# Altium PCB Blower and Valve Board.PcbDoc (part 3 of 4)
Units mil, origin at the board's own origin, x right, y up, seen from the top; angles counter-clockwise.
Board outline 4950 x 3450 mil, 4 copper layers (Top Layer, Signal Layer 1, Signal Layer 2, Bottom Layer), stack 64.4 mil thick; 260 components, 151 nets, 912 pads, 417 vias.
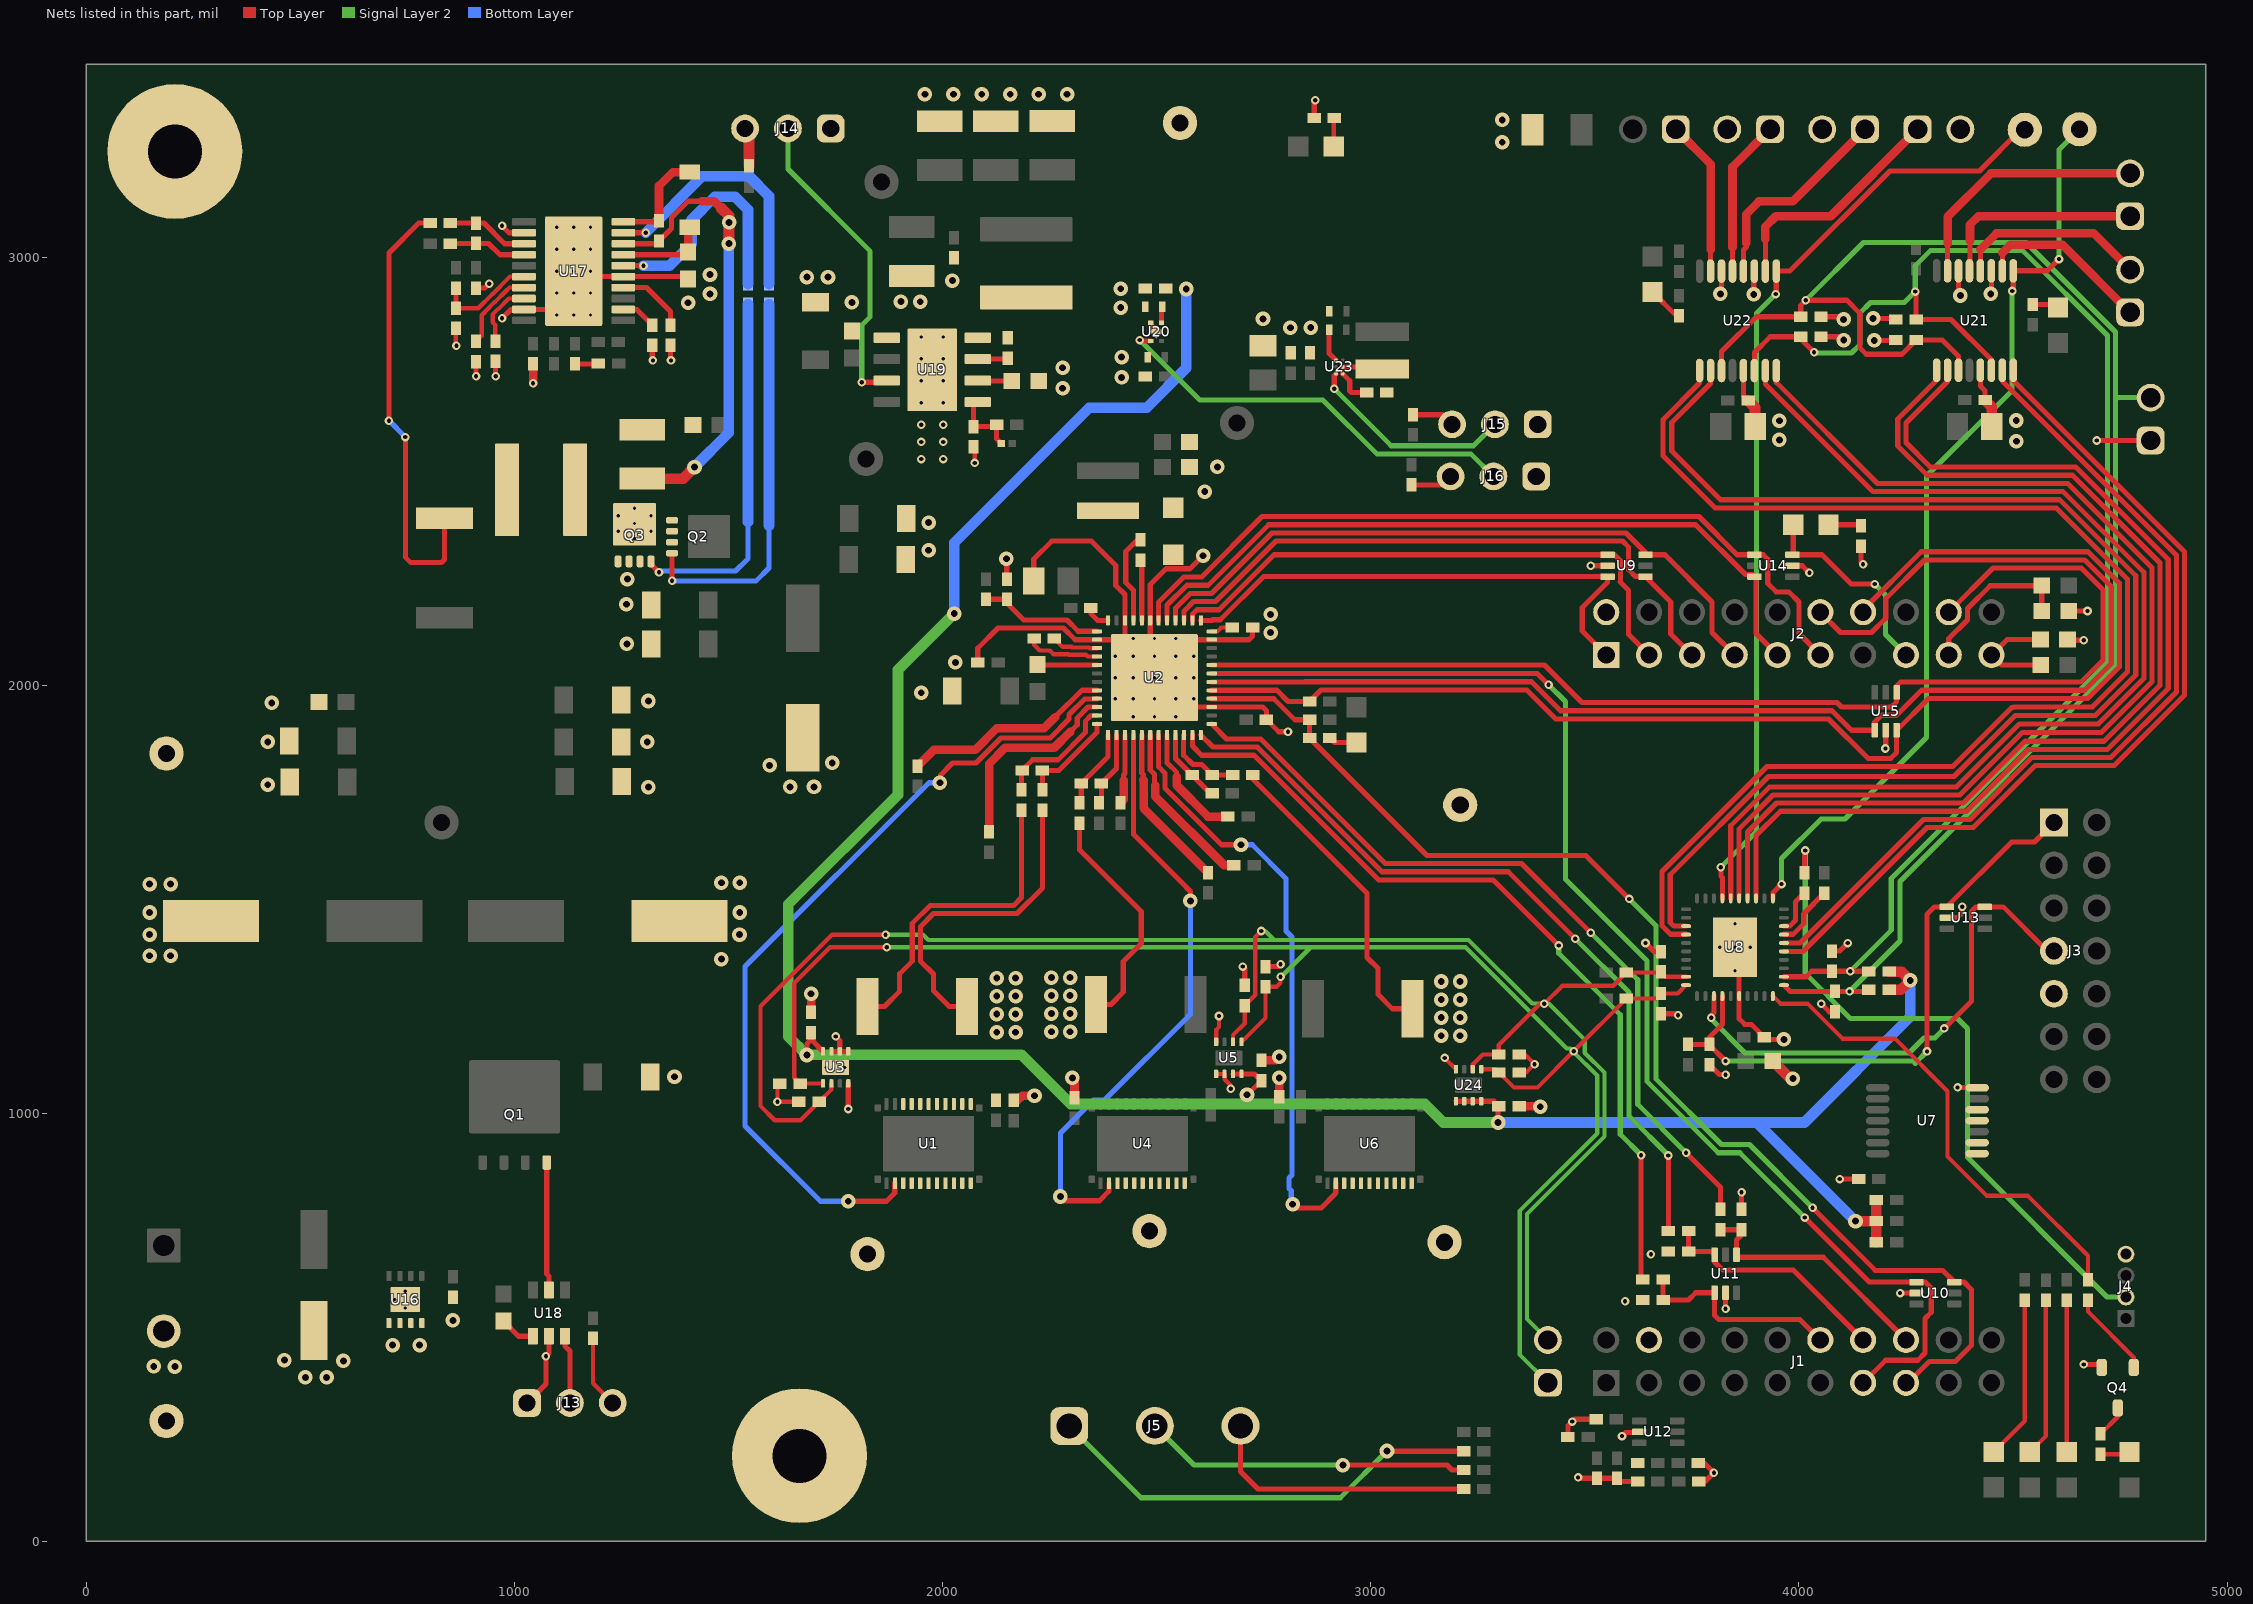
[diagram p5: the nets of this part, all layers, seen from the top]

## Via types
v1: diameter 34, hole 16, Top Layer to Bottom Layer, 186 vias
v2: diameter 20, hole 10, Top Layer to Bottom Layer, 125 vias
v3: diameter 19.68, hole 7.87, Top Layer to Bottom Layer, 94 vias
v4: diameter 19.68, hole 7.87, Top Layer to Bottom Layer, tented both sides, 12 vias

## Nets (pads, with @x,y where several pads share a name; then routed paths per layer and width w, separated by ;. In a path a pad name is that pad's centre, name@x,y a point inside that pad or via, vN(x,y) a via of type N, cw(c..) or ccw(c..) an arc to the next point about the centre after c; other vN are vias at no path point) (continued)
GND: C2.2 C3.2 C4.2 C6.2 C8.2 C9.2 C10.2 C11.2 C12.2 C14.2 C17.2 C19.2 C20.2 C22.2 C23.2 C24.2 C26.2 C27.2 C28.2 C29.2 C30.2 C31.2 C32.2 C33.2 C34.2 C35.2 C36.2 C37.2 C38.2 C39.2 C40.2 C42.2 C43.2 C44.2 C45.2 C46.2 C47.2 C48.2 C49.2 C50.2 C51.2 C52.2 C53.2 C54.2 C55.2 C56.2 C57.2 C59.2 C63.2 C65.2 C66.2 C67.2 C68.2 C71.2 C72.2 C73.2 C74.2 C75.2 C76.2 C77.2 C78.2 C79.2 C80.2 C81.2 C82.2 C83.2 C84.2 C85.2 C86.2 C87.2 C88.2 C89.2 C90.2 C91.2 C92.2 C93.2 C94.2 C95.2 C96.2 D2.2 H1.1 H2.1 J1.4 J2.2 J3.9 J4.4 J6.2 J9.2 J10.2 J11.2 J13.1 J14.1 J15.1 J16.1 Q3.1 Q3.2 Q3.3 Q4.2 R3.1 R4.1 R5.1 R8.1 R12.1 R14.1 R15.1 R16.1 R22.1 R24.1 R25.1 R38.1 R39.1 R47.1 R48.1 R52.1 R53.1 R57.1 R59.1 R60.1 R68.1 R69.1 TP20.1 TP21.1 TP22.1 TP23.1 U2.2 U2.27 U2.35 U2.43 U2.46 U2.49 U3.4 U3.5 U3.6 U3.7 U5.4 U5.5 U5.6 U7.1 U7.2 U7.4 U7.5 U7.7 U8.6 U8.41 U9.2 U10.2 U11.2 U12.2 U13.2 U14.2 U15.2 U16.5 U16.6 U16.7 U16.8 U16.9 U17.2 U17.9 U17.15 U17.21@1138.29,2967.06 U18.2 U19.1 U19.9 U20.2 U20.5 U21.3 U21.6 U21.13 U22.3 U22.6 U22.13 U23.A1 U24.4 | length 8397.9
  Top Layer w10: R47.1@863.01,2833.1 863.01,2794.26 v2(864.45,2792.82) ; C12.2@1620.08,1069.07 1614.17,1063.16 v2(1614.17,1026.98) C11.2@1664.06,1026.98 ; R57.1@2072.27,2556.76 2075.33,2553.69 v2(2075.33,2518.97) ; U5.5@2638.95,1091.91 U5.6@2658.63,1091.91 2658.63,1079.64 2673,1065.27 v2(2673,1057.37) ; U5.4@2638.95,1166.71 2638.95,1194.83 2645.46,1201.34 v2(2645.46,1227.27) ; v2(3172.46,1129.31) U24.4@3198.82,1102.95 ; C96.2@3346.26,1095.08 3362.86,1095.08 v2(3382.64,1114.86) 3360.1,1137.4 C95.2@3346.26,1137.4
  Top Layer w12: v2(910.25,2721.39) C65.2@910.25,2755.69 ; C59.2@910.25,2927.6 910.3,2927.66 930.75,2927.66 v2(940.72,2937.63) ; R53.1@955.71,2756.45 955.71,2722.12 v2(956.43,2721.39) ; v2(970.89,2856.72) 991.66,2877.49 U17.9@1022.14,2877.49 1096.83,2877.49 1138.29,2918.94 v3(1138.29,2967.06) 1151.08,2954.26 U17.15@1254.43,2954.26 1399.48,2954.26 C63.2@1405.39,2948.36 ; v2(970.89,3072.83) 987.11,3056.62 U17.2@1022.14,3056.62 ; J13.1@1029.34,323.43 1073.43,367.52 v2(1073.43,432.77) 1080.24,439.57 U18.2@1080.24,479.36 ; R52.1@1321.88,2793.85 1321.88,2759.86 v2(1323.32,2758.42) ; C66.2@1364.11,2793.85 1364.11,2759.79 v2(1365.48,2758.42) ; U3.7@1740.16,1144.49 U3.6@1759.84,1144.49 ; v2(1750.29,1179.58) 1759.84,1170.03 U3.6@1759.84,1144.49 ; v2(1779.53,1010.02) U3.4@1779.53,1069.68 ; U3.5@1779.53,1144.49 U3.6@1759.84,1144.49 ; R5.1@2056.61,1249.42 2015.28,1249.42 1978.35,1286.35 1978.35,1325.09 1948.13,1355.31 1948.13,1435.81 1978.86,1466.54 2173.92,1466.54 2233.23,1525.85 R16.1@2233.23,1708.3 ; C4.2@2082.17,2052.99 2082.17,2086.1 2129.47,2133.39 2282.31,2133.39 2309.56,2106.14 U2.2@2360.88,2106.14 2406.15,2106.14 U2.49@2425.84,2086.45 ; v1(2148.8,2295.36) 2149.89,2294.26 R22.1@2149.89,2247.87 ; C22.2@2212.96,2243.67 2212.96,2294.38 2254.93,2336.35 2347.46,2336.35 2404.19,2279.62 2404.19,2233.08 2425.84,2211.43 U2.46@2425.84,2151.41 U2.49@2425.84,2086.45 ; R12.1@2319.68,1677.65 2319.68,1615.5 2463.92,1471.26 2463.92,1396.48 2421.9,1354.46 2421.9,1283.01 2393,1254.11 R15.1@2358.51,1254.11 ; U20.2@2485.91,2846.26 2485.91,2842.44 2492.4,2835.96 2492.4,2831.51 U20.5@2498.7,2825.2 ; v1(2608.27,2302.09) 2577.97,2271.79 2521.64,2271.79 2484.89,2235.04 U2.43@2484.89,2151.41 U2.49@2484.89,2027.4 ; v2(2701.23,1342.65) 2705.61,1338.27 C27.2@2705.61,1298.89 ; C9.2@2723.84,2134.68 2723.84,2114.36 2715.62,2106.14 U2.35@2628.59,2106.14 2583.32,2106.14 v3(2544.34,2067.16) v3(2494.73,2017.56) ; R8.1@2724.85,1789.88 2724.85,1780.36 2991.44,1513.78 2991.44,1364.08 3016.74,1338.78 3016.74,1277.92 3050.39,1244.27 R25.1@3097.1,1244.27 ; C28.2@2754.18,1342.65 2783.61,1342.65 v2(2789.39,1348.43) ; v2(2806.66,1891.1) 2784.85,1891.1 2756.82,1919.13 C19.2@2756.15,1919.13 2756.15,1940.03 2747.52,1948.66 U2.27@2628.59,1948.66 2563.63,1948.66 v3(2544.34,1967.95) v3(2494.73,2017.56) ; R59.1@2867.96,3325.03 2867.96,3363.73 v2(2870.38,3366.14) ; C93.2@2902.63,2829.85 2902.63,2775.02 U23.A1@2918.77,2758.88 ; R3.1@3460.63,244.09 3460.63,270.16 v2(3470.47,280) 3475.91,285.43 C6.2@3526.38,285.43 ; v2(3484.25,149.41) 3486.22,147.45 R4.1@3528.35,147.45 C8.2@3575,147.44 3582.5,139.95 R14.1@3623.5,139.95 ; v2(3513.78,2279.01) U9.2@3553.15,2279.01 ; v2(3586.81,246.06) 3594.78,254.03 3625.09,254.03 U12.2@3626.97,255.91 ; v2(3641.73,1397.77) 3661.67,1377.83 C36.2@3677.81,1377.83 ; C37.2@3677.81,1232.58 3714.18,1232.58 v2(3717.76,1229) ; C29.2@3765,182.88 3778.99,182.88 v2(3801.42,160.45) 3780.92,139.95 R24.1@3766.38,139.95 ; C40.2@3790.76,1113.78 3814.33,1090.2 v2(3828.74,1090.2) ; v1(3816.66,2914) 3819.24,2916.58 U22.6@3819.24,2967.17 ; v2(3828.74,543.56) U11.2@3828.74,580.79 ; v3(3850.63,1387.92) 3860.47,1378.08 U8.6@3860.47,1273.75 3860.47,1220.64 3873.33,1207.79 3888.55,1207.79 C35.2@3918.68,1177.66 3923.7,1172.65 v1(3964.8,1172.65) v1@3959.78,1177.66 ; C32.2@3866.09,775.37 v2(3866.09,815.39) ; U22.13@3870.43,2734.88 3870.43,2675.83 C82.2@3881.25,2665 ; v1(3894.36,2912.79) 3894.36,2965.52 U22.3@3896.02,2967.17 ; U14.2@3984.64,2279.01 4007.92,2279.01 v2(4024.65,2262.28) ; C86.2@4051.59,2813.74 4096.9,2813.74 v1(4104.65,2806) ; C85.2@4051.59,2860.54 4098.12,2860.54 v1(4104.33,2854.33) ; v2(4052.01,1256.08) 4070.75,1237.33 C39.2@4084.65,1237.33 ; C38.2@4077.25,1379.04 4095.58,1379.04 v2(4114.17,1397.64) ; v2(4095.58,846.46) C30.2@4139.76,846.46 ; R60.1@4144.77,2324.92 4144.77,2287.49 v2(4149.92,2282.34) ; v1(4173.23,2856.76) 4223.95,2856.76 C84.2@4226.38,2854.33 ; v1(4175.92,2805.12) 4225.49,2805.12 C83.2@4226.38,2806 ; v2(4202,1852.04) 4202.76,1852.8 U15.2@4202.76,1894.69 ; v2(4236.2,580.08) U10.2@4274.61,580.08 ; U13.2@4345.47,1456.63 4370.08,1456.63 4381.31,1467.86 v2(4381.31,1482.22) ; v2(4370.51,1060.35) 4415.52,1060.35 U7.7@4416.34,1059.53 ; U21.6@4372.76,2967.84 4372.76,2918.48 4377.26,2913.97 v1(4377.26,2910.08) ; U21.13@4423.94,2735.56 4423.94,2698.38 4434.77,2687.55 C88.2@4434.77,2665.68 ; v1(4448.2,2914) 4449.53,2915.33 U21.3@4449.53,2967.84 ; R39.1@4627.17,2106.3 4628.46,2105 v2(4665.35,2105) ; R38.1@4630.18,2173.23 v2(4673.99,2173.23) ; v2(4665.35,413.39) 4700.4,413.39 Q4.2@4707.4,406.39 ; U2.49@2425.84,2086.45 v3(2445.13,2067.16) U2.49@2484.89,2027.4 ; U2.49@2484.89,2027.4 v3(2494.73,2017.56)
  Top Layer w20: v2(1043.31,2705.35) R48.1@1043.31,2750.38 ; C10.2@1692.91,1235.47 v1(1692.91,1279.23) ; C2.2@2165.99,1030 2170.85,1034.86 2175.21,1030.49 2185.79,1041.08 v1(2214.57,1041.08) ; C14.2@2308.06,1035.87 v1@2308.06,1076.16 ; C20.2@2744.34,1123.4 2777.67,1123.4 v1(2786.16,1131.89) ; C26.2@2786.16,1038.76 v1(2786.16,1082.85) ; C94.2@3346.26,1016.53 3394.27,1016.53 v1(3395.67,1015.13)
  Top Layer w25: C82.2@3881.25,2665 3897.63,2648.63 C81.2@3897.63,2603.78 ; C34.2@3938.98,1122.05 3979.96,1081.06 v1(3986.09,1081.06) ; C88.2@4434.77,2665.68 4450.51,2649.93 C87.2@4450.51,2604.46
  other v1: 511.5,383.11 561.02,383.11 157.48,408.89 206.69,408.5 600.39,421.84 462.6,423.52 715.45,458.66 778.24,458.66 856.3,516.18 2303.15,1082.68 1373.75,1085.36 3164.71,1181.27 3208.66,1181.27 2126.36,1189.35 2170.31,1189.35 2253.94,1190.53 2297.88,1190.53 3164.71,1223.47 3208.66,1223.47 2126.36,1231.54 2170.31,1231.54 2253.94,1232.72 2297.88,1232.72 3164.71,1265.66 3208.66,1265.66 2126.36,1273.74 2170.31,1273.74 2253.94,1274.91 2297.88,1274.91 3164.71,1307.85 3208.66,1307.85 2126.36,1315.93 2170.31,1315.93 2253.94,1317.1 2297.88,1317.1 1483.28,1360 147.64,1368.11 196.85,1368.11 147.64,1417.45 1525.59,1417.45 147.64,1468.95 1526.16,1468.95 147.64,1535.43 196.85,1535.43 1483.28,1538.38 1526.16,1538.38 1312.65,1761.81 1643.7,1762.5 1699.5,1762.5 423.69,1767.5 1595.7,1812.59 1742.13,1818.26 423.69,1867.31 1310.13,1867.31 433.07,1958.66 1312.65,1962.98 1950.21,1982.12 2029.94,2052.99 1262.54,2096.46 2765.94,2122.69 2765.94,2165.35 1261.47,2188.98 1263.77,2247.87 1967.18,2314.94 1967.18,2379.72 2612.18,2451.94 2641.66,2509.84 4507.87,2569.71 3954.34,2572.96 3954.34,2617.7 4507.79,2618.11 2280.08,2693.64 2417.96,2718.69 2280.32,2741.43 2417.96,2766.14 2812.24,2834.65 2859.8,2835.04 2748.27,2855.45 2415.99,2881.82 1405.39,2893.03 1787.96,2894.03 1947.78,2895.36 1902.39,2895.99 1456.69,2914 2415.99,2926 2022.82,2944.88 1683.07,2953.08 1732.28,2953.08 1456.69,2959.08 3307.09,3268.14 3307.09,3320.34 1958.66,3380 2025.07,3380 2091.48,3380 2157.88,3380 2224.29,3380 2290.7,3380
  other v2: 3593.92,561.17 3654.27,670.97 1950.21,2528.08 2001.39,2528.08 1950.21,2568.18 2001.39,2568.18 1950.21,2608.29 2001.39,2608.29
  other v3: 745.08,545.28 720.47,564.96 769.68,564.96 745.08,584.65 3850.63,1332.8 3815.2,1387.92 3886.06,1387.92 3850.63,1443.04 2445.13,1926.02 2494.73,1926.02 2544.34,1926.02 2403.2,1967.95 2445.13,1967.95 2494.73,1967.95 2586.27,1967.95 2403.2,2017.56 2445.13,2017.56 2544.34,2017.56 2586.27,2017.56 2403.2,2067.16 2494.73,2067.16 2586.27,2067.16 2445.13,2109.09 2494.73,2109.09 2544.34,2109.09 1950.21,2710.82 2001.39,2710.82 1950.21,2762 2001.39,2762 1098.91,2915.88 1138.29,2915.88 1177.65,2915.88 1098.91,2967.06 1177.65,2967.06 1098.91,3018.24 1138.29,3018.24 1177.65,3018.24
  other v4: 1950.21,2659.64 2001.39,2659.64 1950.21,2813.18 2001.39,2813.18 1098.91,2864.69 1138.29,2864.69 1177.65,2864.69 1098.91,3069.42 1138.29,3069.42 1177.65,3069.42
"IN1 DRV8-1": U8.15 U21.16 | length 2108.5
  Top Layer w12: U8.15@3964.8,1378.08 4009.69,1378.08 4299.11,1667.5 4407.27,1667.5 4551.87,1812.09 4736.41,1812.09 4900.63,1976.32 4900.63,2311.46 4500.71,2711.38 U21.16@4500.71,2735.56
"IN1 DRV8-2": U8.25 U22.16 | length 2619.6
  Top Layer w12: U8.25@3860.47,1502.1 3860.47,1664.38 3939.6,1743.5 4375.79,1743.5 4520.39,1888.09 4520.44,1888.09 4522.11,1889.76 4706.59,1889.76 4824.63,2007.8 4824.63,2274.48 4628.13,2470.98 4183.57,2470.98 3947.2,2707.35 U22.16@3947.2,2734.88
"IN2 DRV8-1": U8.16 U21.15 | length 2079.5
  Top Layer w12: U8.16@3964.8,1397.77 4002.5,1397.77 4291.24,1686.5 4399.4,1686.5 4544,1831.09 4728.54,1831.09 4881.63,1984.19 4881.63,2303.59 4475.12,2710.1 U21.15@4475.12,2735.56
"IN2 DRV8-2": U8.26 U22.15 | length 2622.6
  Top Layer w12: U8.26@3840.79,1502.1 3840.79,1671.56 3931.73,1762.5 4367.92,1762.5 4514.87,1909.45 4699.41,1909.45 4805.63,2015.67 4805.63,2263.58 4617.23,2451.98 4172.76,2451.98 3921.61,2703.13 U22.15@3921.61,2734.88
"IN3 DRV8-1": U8.23 U21.10 | length 2487.9
  Top Layer w12: U8.23@3899.84,1502.1 3899.84,1648.66 3956.68,1705.5 4391.53,1705.5 4536.13,1850.09 4720.67,1850.09 4862.63,1992.06 4862.63,2293.48 4646.95,2509.16 4307.53,2509.16 4250,2566.69 4250,2612 4347.17,2709.17 U21.10@4347.17,2735.56
"IN3 DRV8-2": U8.33 U22.10 | length 3094
  Top Layer w12: U8.33@3736.46,1437.14 3708.03,1437.14 3699.46,1445.7 3699.46,1557.11 3928.96,1786.61 4362.51,1786.61 4505.04,1929.13 4692.22,1929.13 4786.63,2023.54 4786.63,2255.4 4609.05,2432.98 3817.02,2432.98 3703,2547 3703,2613.67 3793.65,2704.33 U22.10@3793.65,2734.88
"IN4 DRV8-1": U8.24 U21.9 | length 2486.3
  Top Layer w12: U8.24@3880.16,1502.1 3880.16,1657.19 3947.47,1724.5 4383.66,1724.5 4528.26,1869.09 4712.8,1869.09 4843.63,1999.93 4843.63,2285.61 4639.08,2490.16 4299.66,2490.16 4231,2558.82 4231,2621.5 4321.58,2712.08 U21.9@4321.58,2735.56
"IN4 DRV8-2": U8.34 U22.9 | length 3126.7
  Top Layer w12: U8.34@3736.46,1417.45 3735.77,1418.14 3700.16,1418.14 3680.46,1437.83 3680.46,1564.98 3925.53,1810.04 4359.08,1810.04 4497.17,1948.13 4501.01,1948.13 4501.69,1948.82 4685.04,1948.82 4767.63,2031.41 4767.63,2247.53 4601.18,2413.98 3804.39,2413.98 3682.96,2535.41 3682.96,2620.51 3768.06,2705.61 U22.9@3768.06,2734.88
INHA: J2.1 U2.37 U9.3 | length 1223
  Top Layer w12: U2.37@2603,2151.41 2628.73,2151.41 2630,2152.68 2648.65,2152.68 2749.4,2253.42 U9.3@3553.15,2253.42 3553.15,2240.23 3494.09,2181.18 3494.09,2126.38 J2.1@3550,2070.47
INHB: J2.5 U2.39 U9.4 | length 1460.5
  Top Layer w12: U2.39@2563.63,2151.41 2563.63,2172.67 2586.19,2195.23 2637.46,2195.23 2778.85,2336.61 3588.07,2336.61 3602.36,2322.32 3602.36,2269.38 3618.32,2253.42 U9.4@3641.73,2253.42 3700.79,2194.37 3700.79,2119.68 J2.5@3750,2070.47
INHC: J2.9 U2.41 U14.6 | length 1740.6
  Top Layer w12: U2.41@2524.26,2151.41 2524.26,2187.04 2570.45,2233.23 2620.19,2233.23 2761.57,2374.61 3758.62,2374.61 3875.09,2258.14 3891.34,2258.14 U14.6@3896.06,2253.42 3899.84,2249.64 3899.84,2120.63 J2.9@3950,2070.47
INLA: J2.3 U2.38 U9.1 | length 1325.5
  Top Layer w12: U2.38@2583.32,2151.41 2583.32,2165.49 2594.06,2176.23 2645.33,2176.23 2773.71,2304.61 U9.1@3553.15,2304.61 3569.4,2304.61 3582.88,2291.12 3582.88,2241.11 3582.68,2240.91 3602.36,2221.22 3602.36,2118.11 J2.3@3650,2070.47
INLB: J2.7 U2.40 U9.6 | length 1570.2
  Top Layer w12: U2.40@2543.95,2151.41 2543.95,2179.86 2578.32,2214.23 2628.06,2214.23 2769.44,2355.61 3595.94,2355.61 3641.73,2309.82 U9.6@3641.73,2304.61 3687.12,2304.61 3797.31,2194.41 3797.31,2123.16 J2.7@3850,2070.47
INLC: J2.11 U2.42 U14.4 | length 1881
  Top Layer w12: U2.42@2504.58,2151.41 2504.58,2194.23 2562.58,2252.23 2604.52,2252.23 2745.91,2393.61 3766.49,2393.61 3855.5,2304.61 U14.4@3896.06,2304.61 3916.59,2304.61 3927.17,2294.03 3927.17,2237.66 3946.85,2217.97 3976.38,2217.97 4000,2194.35 4000,2120.47 J2.11@4050,2070.47
ISENA: C32.1 J1.16 R27.2 U11.4 | length 590.8
  Top Layer w12: R27.2@3816.93,728.13 C32.1@3866.09,728.13 3866.09,716.06 3854.33,704.3 U11.4@3854.33,669.37 3860.03,663.67 4056.8,663.67 J1.16@4250,470.47
ISENB: C33.1 J1.14 R28.2 U11.6 | length 550.7
  Top Layer w12: R28.2@3742.36,724.74 C33.1@3742.36,677.17 3795.35,677.17 U11.6@3803.15,669.37 3803.15,652.56 3821.94,633.76 3986.71,633.76 J1.14@4150,470.47
ISENC: C31.1 J1.12 R26.2 U11.1 | length 498.4
  Top Layer w12: R26.2@3682.96,612.11 C31.1@3682.96,564.06 3742.23,564.06 3758.96,580.79 U11.1@3803.15,580.79 3803.15,528.43 3813.6,517.97 4002.5,517.97 J1.12@4050,470.47
LDO3.3: C10.1 C20.1 C79.1 C80.1 C94.1 R6.2 R17.2 R32.2 R33.2 R72.2 U3.8 U5.7 U5.8 U20.1 U24.5 U24.6 U24.7 U24.8 | length 6067.5
  Top Layer w12: v1(1683.07,1136.2) 1683.07,1162.2 1692.91,1172.05 U3.8@1720.47,1144.49 ; U20.1@2511.5,2846.26 2511.5,2882.17 C80.1@2513.19,2883.86 ; U5.7@2678.32,1091.91 U5.8@2698,1091.91 2728.59,1091.91 C20.1@2744.34,1076.16 2711.66,1043.48 v1(2710.88,1043.48) ; U24.5@3198.82,1028.15 U24.6@3218.5,1028.15 U24.7@3238.19,1028.15 U24.8@3257.87,1028.15 3287.41,1028.15 C94.1@3299.02,1016.53 3297.24,1014.76 v1(3297.24,978.52)
  Top Layer w25: v1(4132.1,748.03) R6.2@4180.89,748.03 ; R17.2@4180.89,698.82 R6.2@4180.89,748.03 ; R72.2@4180.89,797.24 R6.2@4180.89,748.03 ; R33.2@4210.61,1288.47 4237.96,1288.47 v1(4259.9,1310.41) 4239.49,1330.82 R32.2@4210.61,1330.82
  Signal Layer 2 w25: v1(2026.98,2167.26) 1895.59,2035.87 1895.59,1743.96 1639.69,1488.06 1639.69,1179.58 v1(1683.07,1136.2) 1683.3,1136.43 2184.18,1136.43 2298.98,1021.63 3125.92,1021.63 3169.03,978.52 v1(3297.24,978.52)
  Bottom Layer w25: v1(2026.98,2167.26) 2026.98,2332.73 2342.34,2648.09 2476.5,2648.09 2569.14,2740.74 v1(2569.14,2925.26) ; v1(3297.24,978.52) 3907.48,978.52 ; v1(4132.1,748.03) 3907.48,972.65 3907.48,978.52 ; v1(4259.9,1310.41) 4259.9,1225.47 4012.94,978.52 3907.48,978.52
LED: D5.1 J2.15 U14.3 | length 487.5
  Top Layer w12: D5.1@3986.63,2374.61 3986.63,2306.59 U14.3@3984.64,2304.61 4053.66,2304.61 4122.25,2236.01 v2(4177.17,2236.01)
  Signal Layer 2 w12: v2(4177.17,2236.01) 4202.36,2210.82 4202.36,2118.11 J2.15@4250,2070.47
MCUON: R67.1 U8.10 | length 1133.1
  Top Layer w10: U8.10@3939.21,1273.75 3956.88,1256.08 4020.24,1256.08 4101.92,1174.4 4224.37,1174.4 4347.17,1051.6 4347.17,898.9 4438.98,807.09 4535.28,807.09 4675.15,667.22 R67.1@4675.15,610.71
MOTA: J5.1 R2.2 TP2.1 U1.3 U1.4 U1.5 U1.6 U1.7 U1.8 U1.9 U1.10 U1.11 | length 1036.3
  Top Layer w12: v1(3037.87,211.2) 3038.47,210.6 R2.2@3217.13,210.6
  Signal Layer 2 w12: J5.1@2295.7,269.86 2463.42,102.13 2928.8,102.13 v1(3037.87,211.2)
MOTB: J5.2 R11.2 TP8.1 U4.3 U4.4 U4.5 U4.6 U4.7 U4.8 U4.9 U4.10 U4.11 | length 764.2
  Top Layer w12: v1(2935.04,178.43) 3177.87,178.43 3189.68,166.62 R11.2@3217.13,166.62
  Signal Layer 2 w12: J5.2@2495.7,269.86 2587.12,178.43 v1(2935.04,178.43)
MOTC: J5.3 R23.2 TP11.1 U6.3 U6.4 U6.5 U6.6 U6.7 U6.8 U6.9 U6.10 U6.11 | length 644.8
  Top Layer w12: J5.3@2695.7,269.86 2695.7,163.36 2736.42,122.63 R23.2@3217.13,122.63
NetC5_2: C5.2 U2.5 | length 140.1
  Top Layer w12: C5.2@2221.11,2048 2222.03,2047.08 U2.5@2360.88,2047.08
NetC7_1: C7.1 U2.4 | length 173
  Top Layer w10: C7.1@2213.93,2108.58 2213.93,2093.64 2226.75,2080.81 2250.22,2080.81 2258.59,2072.44 2293.76,2072.44 2295.07,2071.14 2334.66,2071.14 2339.03,2066.77 U2.4@2360.88,2066.77
NetC7_2: C7.2 U2.3 | length 108.9
  Top Layer w10: C7.2@2261.17,2108.58 2280.32,2089.44 2300.8,2089.44 2302.11,2088.14 2341.7,2088.14 2343.39,2086.45 U2.3@2360.88,2086.45
NetC9_1: C9.1 U2.36 | length 51.7
  Top Layer w10: U2.36@2628.59,2125.82 2642.15,2125.82 2651.01,2134.68 C9.1@2676.6,2134.68
NetC15_1: C15.1 R7.2 U2.21 | length 173.4
  Top Layer w12: U2.21@2543.95,1883.7 2543.95,1828.54 C15.1@2582.61,1789.88 2621.98,1750.51 R7.2@2629.85,1750.51
NetC15_2: C15.2 R8.2 U2.22 | length 181.5
  Top Layer w12: U2.22@2563.63,1883.7 2562.95,1883.01 2562.95,1836.41 2584.67,1814.69 2605.04,1814.69 C15.2@2629.85,1789.88 R8.2@2677.61,1789.88
NetC16_1: C16.1 R9.2 U2.14 | length 175.9
  Top Layer w12: R9.2@2364.96,1724.9 2370.86,1730.8 C16.1@2370.86,1770.17 2406.15,1805.46 U2.14@2406.15,1883.7
NetC16_2: C16.2 R12.2 U2.13 | length 186.5
  Top Layer w12: R12.2@2319.68,1724.9 2323.62,1728.83 C16.2@2323.62,1770.17 2386.47,1833.02 U2.13@2386.47,1883.7
NetC18_1: C18.1 R13.2 U2.11 | length 289.6
  Top Layer w12: R13.2@2184.3,1755.54 2184.3,1799.64 C18.1@2185.68,1801.02 2210.49,1825.83 2269.83,1825.83 2333.32,1889.32 2333.32,1915.49 2346.8,1928.97 U2.11@2360.88,1928.97
NetC18_2: C18.2 R16.2 U2.12 | length 229.7
  Top Layer w12: R16.2@2233.23,1755.54 2233.23,1800.71 C18.2@2232.92,1801.02 2271.89,1801.02 2360.88,1890.01 U2.12@2360.88,1909.29
NetC21_1: C21.1 U2.44 | length 141.8
  Top Layer w12: C21.1@2462.58,2292.15 2465.21,2289.52 U2.44@2465.21,2151.41
NetC21_2: C21.2 D2.1 L1.1 U2.45 | length 214.2
  Top Layer w12: U2.45@2445.52,2151.41 2445.52,2221.76 2427.81,2239.48 2427.81,2312.21 2454.99,2339.4 C21.2@2462.58,2339.4
NetC41_2: C41.2 R41.2
NetC58_1: C58.1 R46.1 U17.3 | length 191.6
  Top Layer w12: R46.1@850.44,3079.18 910.26,3079.18 C58.1@910.3,3079.13 928.53,3079.13 976.63,3031.03 U17.3@1022.14,3031.03
NetC58_2: C58.2 R45.1 U17.4 | length 183
  Top Layer w12: R45.1@850.44,3031.03 851.3,3031.89 C58.2@910.3,3031.89 939.6,3031.89 966.05,3005.44 U17.4@1022.14,3005.44
NetC60_2: C60.2 U18.1 | length 83
  Top Layer w12: C60.2@974.41,514.6 1009.65,479.36 U18.1@1042.83,479.36
NetC61_2: C61.2 R51.2 | length 54.5
  Top Layer w12: C61.2@1141.7,2750.19 1194.47,2750.19 R51.2@1195.72,2751.44
NetC63_1: C63.1 D3.2 U17.17 | length 213.1
  Top Layer w12: U17.17@1254.43,3005.44 1399.48,3005.44 C63.1@1405.39,3011.35
  Top Layer w20: C63.1@1405.39,3011.35 1405.39,3065.99 D3.2@1408.95,3069.55
NetC64_1: C64.1 L2.2 Q2.1 Q2.2 Q2.3 Q3.5 Q3.6 Q3.7 Q3.8 Q3.9 R41.1 U17.18 | length 1119.1
  Top Layer w12: U17.18@1254.43,3031.03 1331.22,3031.03 C64.1@1337.59,3037.4 1366.95,3066.76 1366.95,3092.02 1405.35,3130.41 1437.5,3130.41
  Top Layer w20: 1437.5,3130.41 1466.54,3130.41 1482.56,3114.39
  Top Layer w25: R41.1@1298.94,2482.38 1393.42,2482.38 v1(1420.41,2509.38) ; 1482.56,3114.39 1501.29,3095.66 v1(1501.29,3080.71) 1501.29,3032.13 v1(1500.65,3031.5)
  Bottom Layer w25: v1(1420.41,2509.38) 1500.65,2589.61 v1(1500.65,3031.5) 1500.65,3080.07 v1(1501.29,3080.71)
  other v3: 1280.39,2341.93 1242,2359.74 1318.77,2359.74 1280.39,2377.56 1242,2395.37 1318.77,2395.37
  other v4: 1280.39,2413.19
NetC64_2: C64.2 D3.1 U17.20 | length 250.2
  Top Layer w12: U17.20@1254.43,3082.21 1335.16,3082.21 C64.2@1337.59,3084.65
  Top Layer w20: C64.2@1337.59,3084.65 1337.59,3165.82 1370.27,3198.49 D3.1@1408.95,3198.49
NetC65_1: C65.1 U17.7 | length 192.3
  Top Layer w10: C65.1@910.25,2802.94 923.72,2816.4 923.72,2864.15 931.89,2872.32 931.89,2872.88 954.74,2895.72 955.29,2895.72 979.65,2920.08 988.24,2928.67 U17.7@1022.14,2928.67
NetC66_1: C66.1 U17.14 | length 164.6
  Top Layer w12: U17.14@1254.43,2928.67 1308.29,2928.67 1364.11,2872.86 C66.1@1364.11,2841.09
NetC69_1: C69.1 U19.7 | length 71
  Top Layer w12: U19.7@2082.1,2761.41 2149.3,2761.41 C69.1@2151.97,2764.08
NetC69_2: C69.2 L3.1 U19.8
NetC70_2: C70.2 R56.1 R57.2 U19.5 | length 165.4
  Top Layer w12: U19.5@2082.1,2661.41 2072.27,2651.58 R57.2@2072.27,2604 2121.88,2604 R56.1@2126.15,2608.27 2126.15,2575.07 C70.2@2136.78,2564.44
NetC76_1: C76.1 U19.6 | length 79.6
  Top Layer w12: U19.6@2082.1,2711.41 2082.69,2710.82 C76.1@2161.48,2710.82
NetD1_2: D1.2 R18.2 | length 66.6
  Top Layer w12: R18.2@2904.37,1876.74 2915.32,1865.8 D1.2@2966.39,1865.8
NetD4_2: D4.2 R59.2 | length 67.9
  Top Layer w10: D4.2@2913.32,3257.87 2913.32,3323.14 R59.2@2915.21,3325.03
NetD5_2: D5.2 R60.2 | length 76.5
  Top Layer w12: D5.2@4069.31,2374.61 4142.32,2374.61 R60.2@4144.77,2372.16
NetD6_2: D6.2 R61.2 | length 370
  Top Layer w10: D6.2@4539.37,208.66 4576.77,246.06 R61.2@4576.77,563.14
NetD7_2: D7.2 R62.2 | length 354.8
  Top Layer w10: D7.2@4625.67,208.66 R62.2@4625.67,563.46
NetD8_2: D8.2 R63.2 | length 69.6
  Top Layer w10: R63.2@4704.72,203.86 4767.56,203.86 D8.2@4772.36,208.66
NetD9_2: D9.2 R64.2 | length 62.1
  Top Layer w12: R64.2@4546.24,2889.1 4598.02,2889.1 D9.2@4605.3,2881.82
NetD10_2: D10.2 R65.2 | length 84.8
  Top Layer w12: D10.2@3658.09,2918.48 3713.73,2862.84 R65.2@3719.84,2862.84
NetD11_2: D11.2 R73.2 | length 384.5
  Top Layer w10: D11.2@4454.95,209.02 4527.56,281.63 R73.2@4527.56,563.46
NetJ2_17: J2.17 R36.1 R38.2 | length 381.3
  Top Layer w12: J2.17@4350,2070.47 4350,2108.94 4393.51,2152.45 4393.51,2178.94 4446.82,2232.25 R36.1@4567.19,2232.25 R38.2@4567.19,2173.23
NetJ2_19: J2.19 R37.1 R39.2 | length 253.6
  Top Layer w12: R39.2@4564.17,2106.3 4485.83,2106.3 J2.19@4450,2070.47 4473.23,2047.24 R37.1@4564.96,2047.24
NetJ7_1: J7.1 U21.2 | length 413.2
  Top Layer w12: U21.2@4475.12,2967.84 4475.12,3009.57
  Top Layer w20: 4475.12,3009.57 4493.79,3028.24 4616.04,3028.24 J7.1@4773.62,2870.65
NetJ7_2: J7.2 U21.4 | length 450.2
  Top Layer w12: U21.4@4423.94,2967.84 4423.94,3017.9
  Top Layer w20: 4423.94,3017.9 4461.27,3055.24 4689.04,3055.24 J7.2@4773.62,2970.65
NetJ8_1: J8.1 U21.5 | length 490.6
  Top Layer w12: U21.5@4398.35,2967.84 4399.61,2969.1 4399.61,3038.12
  Top Layer w20: 4399.61,3038.12 4399.61,3075.71 4419.29,3095.4 J8.1@4773.62,3095.4
NetJ8_2: J8.2 U21.7 | length 594.7
  Top Layer w12: U21.7@4347.17,2967.84 4347.17,3031.5
  Top Layer w20: 4347.17,3031.5 4347.17,3094.11 4448.45,3195.4 J8.2@4773.62,3195.4
NetJ9_1: J9.1 U22.2 | length 553.8
  Top Layer w12: U22.2@3921.61,2967.17 3921.61,3041.34
  Top Layer w20: 3921.61,3041.34 3921.61,3071.17 3945.83,3095.4 4074.21,3095.4 J9.1@4277.26,3298.45
NetJ10_1: J10.1 U22.4 | length 495.2
  Top Layer w12: U22.4@3870.43,2967.17 3870.43,3016.21 3877.32,3023.1 3877.32,3032.36
  Top Layer w20: 3877.32,3032.36 3877.32,3100.39 3906.84,3129.92 3985.83,3129.92 J10.1@4154.36,3298.45
NetJ11_1: J11.1 U22.5 | length 367.7
  Top Layer w12: U22.5@3844.84,2967.17 3844.84,3023.1
  Top Layer w20: 3844.84,3023.1 3844.84,3210.51 J11.1@3932.77,3298.45
NetJ12_1: J12.1 U22.7 | length 365
  Top Layer w12: U22.7@3793.65,2967.17 3793.65,3017
  Top Layer w20: J12.1@3712.34,3298.45 3793.65,3217.14 3793.65,3017
NetJ13_2: J13.2 U18.3 | length 160.8
  Top Layer w12: U18.3@1117.64,479.36 1117.64,456.27 1129.34,444.56 J13.2@1129.34,323.43
NetJ13_3: J13.3 R54.1 | length 175.6
  Top Layer w10: R54.1@1183.21,474.47 1183.21,369.57 J13.3@1229.34,323.43
  Top Layer w12: R54.1@1179.34,470.61 R54.1@1183.21,474.47
NetJ14_2: J14.2 U19.3 | length 741.5
  Top Layer w12: v2(1811.02,2707.35) 1839.48,2707.35 1844.45,2712.32 1845.36,2711.41 U19.3@1869.5,2711.41
  Signal Layer 2 w12: J14.2@1638.59,3300.18 1638.59,3205.42 1830.71,3013.3 1830.71,2860.24 1811.02,2840.56 v2(1811.02,2707.35)
NetJ14_3: J14.3 R55.1 | length 91.2
  Top Layer w25: J14.3@1538.59,3300.18 1547.7,3291.07 R55.1@1547.7,3212.79
NetJ15_2: J15.2 U23.C1 | length 487.7
  Top Layer w12: v2(2914.81,2692.12) 2914.84,2723.45 U23.C1@2918.77,2727.38
  Signal Layer 2 w12: v2(2914.81,2692.12) 3047.69,2559.24 3239.88,2559.24 J15.2@3289.88,2609.24
NetJ15_3: J15.3 R70.1 | length 100.2
  Top Layer w12: R70.1@3098.96,2631.65 3167.47,2631.65 J15.3@3189.88,2609.24
NetJ16_2: J16.2 U20.3 | length 983.8
  Top Layer w12: v2(2460.63,2806) 2462.5,2804.14 U20.3@2485.91,2804.14
  Signal Layer 2 w12: v2(2460.63,2806) 2600.96,2665.68 2888.7,2665.68 3014.13,2540.24 3233.73,2540.24 J16.2@3286.47,2487.5
NetJ16_3: J16.3 R71.1 | length 109.1
  Top Layer w12: R71.1@3095.55,2467.57 3183.56,2467.57 3186.47,2470.48 J16.3@3186.47,2487.5
NetL2_1: L2.1 R40.2 R46.2 | length 1048
  Top Layer w12: v2(706.69,2617.87) 706.69,3009.38 776.49,3079.18 R46.2@803.19,3079.18 ; v2(745.08,2579.48) 745.08,2298.92 757.87,2286.12 829.43,2286.12 836.61,2293.31 R40.2@836.61,2389.76
  Bottom Layer w12: v2(706.69,2617.87) v2(745.08,2579.48)
NetL4_1: L4.1 U23.B2 | length 94.4
  Top Layer w12: U23.B2@2934.52,2743.13 3021.7,2743.13 L4.1@3026.79,2738.04
NetQ1_4: Q1.4 U18.5 | length 299.4
  Top Layer w12: Q1.4@1075.49,885.04 1075.49,624.71 1080.24,619.96 U18.5@1080.24,587.63
NetQ2_4: Q2.4 R50.2 | length 919.5
  Top Layer w12: Q2.4@1368.01,2308.28 1368.01,2267.23 1368.11,2267.13 v2(1368.11,2243.67)
  Bottom Layer w12: v2(1368.11,2243.67) 1564.45,2243.67 1594.49,2273.71 1594.49,2372.94
  Bottom Layer w25: 1594.49,2372.94 R50.2@1594.49,2889.76
NetQ3_4: Q3.4 R49.2 | length 848.2
  Top Layer w12: Q3.4@1318.77,2289.07 1318.77,2282.6 v2(1337.59,2263.78)
  Bottom Layer w12: v2(1337.59,2263.78) 1340.49,2266.67 1516.46,2266.67 1545.28,2295.48 1545.28,2381.89
  Bottom Layer w25: 1545.28,2381.89 R49.2@1545.28,2889.76
NetQ4_1: Q4.1 R67.2 | length 201.4
  Top Layer w10: R67.2@4675.15,563.46 4675.15,536.96 4782.2,429.91 Q4.1@4782.2,406.39
NetQ4_3: Q4.3 R63.1 | length 77.4
  Top Layer w10: R63.1@4704.72,251.1 4744.8,291.18 Q4.3@4744.8,311.9
NetR20_1: R20.1 U2.48 | length 59.9
  Top Layer w12: R20.1@2346.46,2180.26 2346.46,2166.65 2361.69,2151.41 U2.48@2386.47,2151.41
NetR21_1: R21.1 R22.2 U2.1 | length 290.8
  Top Layer w12: R21.1@2101.03,2200.63 2141.08,2200.63 2189.31,2152.39 2290.18,2152.39 2316.75,2125.82 U2.1@2360.88,2125.82
NetR29_1: R29.1 U8.18 | length 105.3
  Top Layer w12: U8.18@3964.8,1437.14 3978.71,1437.14 3992.34,1450.76 3992.34,1493.88 R29.1@4012.84,1514.38
NetR34_1: R34.1 U8.17 | length 148.3
  Top Layer w12: U8.17@3964.8,1417.45 3965.49,1418.14 3986.58,1418.14 4011.34,1442.89 4011.34,1465.49 4012.84,1466.99 4012.84,1468.11 R34.1@4059.11,1514.38
NetR42_1: R42.1 U2.8 | length 493.5
  Top Layer w12: 2262.77,1924.88 2262.77,1925.55 2325.25,1988.03 U2.8@2360.88,1988.03
  Top Layer w20: R42.1@1941.19,1810.77 1979.61,1849.19 2076.46,1849.19 2126.94,1899.67 2237.55,1899.67 2262.77,1924.88
NetR43_1: R43.1 R47.2 U17.6 | length 237
  Top Layer w10: R47.2@863.01,2880.34 915.32,2880.34 947.7,2912.72 948.25,2912.72 989.79,2954.26 U17.6@1022.14,2954.26
  Top Layer w12: R47.2@863.01,2880.34 R43.1@863.01,2927.6
NetR49_1: R49.1 U17.16 | length 576.1
  Top Layer w12: U17.16@1254.43,2979.85 v2(1301.38,2979.85)
  Bottom Layer w25: v2(1301.38,2979.85) 1361.93,2979.85 1413.3,3031.22 1413.3,3086.37 1467.9,3140.98 1514.93,3140.98 1545.28,3110.63 R49.1@1545.28,2937.01
NetR50_1: R50.1 U17.19 | length 619.4
  Top Layer w12: U17.19@1254.43,3056.62 v2(1306.47,3056.62)
  Bottom Layer w25: v2(1306.47,3056.62) 1438.82,3188.98 1547.7,3188.98 1594.49,3142.19 R50.1@1594.49,2937.01
NetR52_2: R52.2 U17.12 | length 82.5
  Top Layer w12: U17.12@1254.43,2877.49 1285.49,2877.49 R52.2@1321.88,2841.09
NetR53_2: R53.2 U17.8 | length 153.6
  Top Layer w10: R53.2@955.71,2803.69 955.36,2804.04 955.36,2841.14 948.89,2847.61 948.89,2865.83 961.78,2878.72 962.33,2878.72 986.69,2903.08 U17.8@1022.14,2903.08
NetR69_2: R69.2 U23.C2 | length 88.6
  Top Layer w12: U23.C2@2934.52,2727.38 2950.8,2711.11 2950.8,2686.92 2954.58,2683.14 R69.2@2990.62,2683.14
NetR74_1: R74.1 U2.10 | length 475.3
  Top Layer w12: 2297.59,1890.59 2314.32,1907.32 2314.32,1923.36 2339.62,1948.66 U2.10@2360.88,1948.66
  Top Layer w20: R74.1@2108.51,1657.48 2108.51,1816.19 2145.99,1853.67 2260.66,1853.67 2297.59,1890.59
NetR75_1: R75.1 U2.17 | length 385.8
  Top Layer w12: U2.17@2465.21,1883.7 2465.21,1794.8 2468.57,1791.44 2468.57,1778.48
  Top Layer w20: 2468.57,1778.48 2469.31,1777.73 2469.31,1712.66 R75.1@2619.97,1562.01
NetR76_1: R76.1 U2.15 | length 163.3
  Top Layer w12: 2422.52,1777.73 2422.52,1790.43 2425.84,1793.75 U2.15@2425.84,1883.7
  Top Layer w20: R76.1@2415,1724.9 2422.52,1732.41 2422.52,1777.73
NetR77_1: R77.1 U2.18 | length 398.7
  Top Layer w12: U2.18@2484.89,1883.7 2484.89,1801.98 2494.73,1792.14 2494.73,1767.54 2496.31,1765.96
  Top Layer w20: 2496.31,1765.96 2496.31,1740.56 2657.64,1579.23 R77.1@2680.29,1579.23
NetR78_1: R78.1 U2.20 | length 277.1
  Top Layer w12: U2.20@2524.26,1883.7 2524.26,1818.86 2546.59,1796.53 2546.59,1785.43
  Top Layer w20: 2546.59,1785.43 2546.59,1765.98 2619.66,1692.91 R78.1@2666.51,1692.91
nFAULT: J1.15 R18.1 R19.1 U2.28 U10.6 | length 2900
  Top Layer w12: U2.28@2628.59,1968.34 2773.47,1968.34 2822.68,1919.13 R19.1@2857.12,1919.13 R18.1@2857.12,1876.74 3131.59,1602.28 3501.96,1602.28 v2(3603.47,1500.76) ; v2(4031.87,779.4) 4178.05,633.23 4335.63,633.23 U10.6@4363.19,605.67 4385.29,605.67 4403.24,587.72 4403.24,458.32 4365.39,420.47 4304.6,420.47 4254.61,370.47 J1.15@4250,370.47
  Signal Layer 2 w12: v2(3603.47,1500.76) 3665.81,1438.42 3665.81,1080.52 3819.38,926.95 3884.32,926.95 v2(4031.87,779.4)
RXD: J4.2 R29.2 | length 1578.2
  Top Layer w12: R29.2@4012.84,1561.62 4012.84,1611.68 v2(4014.95,1613.78)
  Signal Layer 2 w12: v2(4014.95,1613.78) 4014.95,1326.88 4120.11,1221.71 4370.18,1221.71 4393.51,1198.38 4393.51,897.35 4719.89,570.97 J4.2@4763.78,570.97
"SBW TCK": J3.7 U8.3 U13.6 | length 1196.1
  Top Layer w12: v2(3795.35,1223.47) 3795.35,1228.98 3801.42,1235.04 U8.3@3801.42,1273.75 ; v2(4339.38,1198.16) 4403.17,1261.95 4403.17,1471.59 4413.8,1482.22 U13.6@4434.06,1482.22 4477.03,1482.22 4580.02,1379.23 J3.7@4595.67,1379.23
  Signal Layer 2 w12: v2(3795.35,1223.47) 3795.35,1219.94 3874.25,1141.05 4257.31,1141.05 4292.18,1175.92 4317.13,1175.92 v2(4339.38,1198.16)
"SBW TDIO": C40.1 J3.1 R35.2 U8.4 U13.1 | length 1418.9
  Top Layer w12: R35.2@3741.38,1161.02 C40.1@3790.76,1161.02 ; U8.4@3821.1,1273.75 3821.1,1207.38 3790.76,1177.03 C40.1@3790.76,1161.02 ; v2(3828.74,1122.05) 3790.76,1160.03 C40.1@3790.76,1161.02 ; v2(4299.21,1144.49) 4299.21,1464.69 4316.74,1482.22 U13.1@4345.47,1482.22 4497.11,1633.86 4550.3,1633.86 J3.1@4595.67,1679.23
  Signal Layer 2 w12: v2(3828.74,1122.05) 4266.48,1122.05 4271.63,1116.9 v2(4299.21,1144.49)
SCL1: C39.1 C83.1 C85.1 J17.2 R33.1 U8.11 U21.11 U22.11 | length 3777.8
  Top Layer w12: U22.11@3819.24,2734.88 3819.24,2779.15 3900.63,2860.54 C85.1@4004.34,2860.54 4004.34,2887.13 v2(4016.16,2898.94) 4112.2,2898.94 4142.32,2868.83 4142.32,2787.85 4157.21,2772.96 4240.58,2772.96 C83.1@4273.62,2806 4334.79,2806 4372.76,2768.04 U21.11@4372.76,2735.56 ; U8.11@3964.8,1299.34 3979.57,1284.58 C39.1@4084.65,1284.58 v2(4118.36,1284.58) 4159.47,1284.58 R33.1@4163.37,1288.47
  Signal Layer 2 w12: v2(4016.16,2898.94) 4151.02,3033.81 4530.46,3033.81 4739.67,2824.6 4739.67,2667.32 ; v2(4118.36,1284.58) 4236.04,1402.25 4236.04,1541.68 4739.67,2045.31 4739.67,2667.32 ; J17.2@4821.51,2671.5 4743.84,2671.5 4739.67,2667.32
SCL2: C11.1 C27.1 C36.1 C95.1 J18.2 R30.1 U3.2 U5.2 U8.39 U24.2 | length 4309.7
  Top Layer w10: U3.2@1740.16,1069.68 1740.16,1055.83 C11.1@1711.31,1026.98 1667.93,983.61 1608.07,983.61 1574.8,1016.88 1574.8,1249.84 1742.29,1417.32 v2(1866.63,1417.32) ; U5.2@2678.32,1166.71 2678.32,1182.61 2705.61,1209.9 C27.1@2705.61,1251.65 2730.37,1276.41 2730.37,1411.8 v2(2744.34,1425.77) ; U24.2@3238.19,1102.95 3238.19,1114.04 3261.55,1137.4 C95.1@3299.02,1137.4 3299.02,1159.42 3395.68,1256.08 v2(3405.51,1256.08) 3447.47,1298.04 3566.54,1298.04 R30.1@3597.24,1328.74 3675.97,1328.74 C36.1@3677.81,1330.58 3689.37,1319.03 U8.39@3736.46,1319.03
  Signal Layer 2 w10: v2(1866.63,1417.32) 1953.87,1417.32 1966.4,1404.8 2774.53,1404.8 ; v2(2744.34,1425.77) 2753.56,1425.77 2774.53,1404.8 ; J18.2@3413.61,470.47 3364.64,519.43 3364.64,764.93 3545.85,946.14 3545.85,1095.09 3499.54,1141.41 3499.54,1172.09 3415.54,1256.08 v2(3405.51,1256.08) 3405.39,1256.2 3377.1,1256.2 3228.5,1404.8 2774.53,1404.8
SCLK: J1.13 U2.31 U10.1 | length 3014.5
  Top Layer w12: U2.31@2628.59,2027.4 3388.96,2027.4 v2(3415.35,2001) ; v2(4013.52,756.45) 4164.3,605.67 U10.1@4274.61,605.67 4295.14,605.67 4309.06,591.75 4309.06,535.11 4294.76,520.82 4294.76,440.21 4277.68,423.12 4202.65,423.12 J1.13@4150,370.47
  Signal Layer 2 w12: v2(3415.35,2001) 3454.72,1961.63 3454.72,1546.67 3645.56,1355.83 3645.56,1073.9 3811.51,907.95 3862.02,907.95 v2(4013.52,756.45)
SCS: J2.18 U2.32 U15.4 | length 2778.3
  Top Layer w12: U2.32@2628.59,2047.08 3405.67,2047.08 3493.5,1959.25 4089.25,1959.25 4099.68,1948.82 4215.76,1948.82 4228.35,1961.4 U15.4@4228.35,1983.27 4228.35,1998.43 4237.63,2007.71 4659.68,2007.71 4710.63,2058.67 4710.63,2222.5 4659.51,2273.62 4453.15,2273.62 J2.18@4350,2170.47
SD_N: J2.14 R10.1 U2.29 U15.3 | length 3213
  Top Layer w12: U2.29@2628.59,1988.03 2780.66,1988.03 2806.64,1962.04 R10.1@2857.12,1962.04 2883.95,1988.87 3364.41,1988.87 3432.03,1921.25 4069.38,1921.25 4161.59,1829.04 4214.42,1829.04 4228.35,1842.97 U15.3@4228.35,1894.69 4302.69,1969.03 4674.73,1969.03 4748.63,2042.93 4748.63,2238.24 4675.25,2311.62 4285.78,2311.62 4150,2175.84 J2.14@4150,2170.47
SD_P: J2.12 U2.30 U15.1 | length 3225.2
  Top Layer w12: U2.30@2628.59,2007.71 2846.57,2007.87 3375.73,2007.87 3443.35,1940.25 4077.25,1940.25 4122.82,1894.69 U15.1@4177.17,1894.69 4177.17,1913.78 4193.21,1929.82 4228.21,1929.82 4286.42,1988.03 4666.86,1988.03 4729.63,2050.8 4729.63,2230.37 4667.38,2292.62 4293.65,2292.62 4202.76,2201.72 4202.76,2156.24 4169.68,2123.16 4097.31,2123.16 J2.12@4050,2170.47
SDA1: C38.1 C84.1 C86.1 J17.1 R32.1 U8.12 U21.14 U22.14 | length 3554.2
  Top Layer w12: U22.14@3896.02,2734.88 3896.02,2776.91 3932.85,2813.74 C86.1@4004.34,2813.74 4004.34,2808.58 v2(4035.43,2777.49) ; U8.12@3964.8,1319.03 4017.26,1319.03 4030.03,1331.8 C38.1@4077.25,1331.8 v2(4119.82,1331.8) 4162.38,1331.8 R32.1@4163.37,1330.82 ; v2(4271.65,2919.29) 4273.62,2917.32 C84.1@4273.62,2854.33 4355.46,2854.33 4449.53,2760.26 U21.14@4449.53,2735.56 ; v2(4695.67,2571.5) J17.1@4821.51,2571.5
  Signal Layer 2 w12: v2(4035.43,2777.49) 4036.92,2776 4123.05,2776 4142.32,2795.28 4142.32,2868.83 4167.19,2893.7 4246.06,2893.7 v2(4271.65,2919.29) 4271.65,2979.46 4307,3014.81 4522.59,3014.81 4720.67,2816.73 4720.67,2571.5 ; v2(4119.82,1331.8) 4215.76,1427.74 4215.76,1548.28 4720.67,2053.18 4720.67,2571.5 ; v2(4695.67,2571.5) 4720.67,2571.5
SDA2: C12.1 C28.1 C37.1 C96.1 J18.1 R31.1 U3.1 U5.1 U8.40 U24.1 | length 4041.9
  Top Layer w10: U3.1@1720.47,1069.68 1667.94,1069.68 C12.1@1667.32,1069.07 1653.23,1083.16 1653.23,1304.22 1736.8,1387.8 v2(1869.5,1387.8) ; U5.1@2698,1166.71 2754.18,1222.89 C28.1@2754.18,1288.16 ; C28.1@2754.18,1295.4 2779.69,1295.4 2789.39,1305.1 v2(2789.39,1318.9) ; U24.1@3257.87,1102.95 3291.15,1102.95 C96.1@3299.02,1095.08 3299.72,1095.08 3334.45,1060.35 3389.27,1060.35 v2(3473.88,1144.96) R31.1@3596.93,1268.01 3666,1268.01 C37.1@3677.81,1279.82 3716.94,1279.82 U8.40@3736.46,1299.34
  Signal Layer 2 w10: v2(1869.5,1387.8) 2859.87,1387.8 ; v2(2789.39,1318.9) 2790.97,1318.9 2859.87,1387.8 ; J18.1@3413.61,370.47 3347.64,436.43 3347.64,771.97 3528.85,953.18 3528.85,1088.05 3473.88,1143.02 v2(3473.88,1144.96) 3467.27,1151.57 3457.68,1151.57 3221.46,1387.8 2859.87,1387.8
SHA: U1.2 U2.9 | length 1922.4
  Top Layer w12: v1(1779.53,794.68) 1868.92,794.68 1888.23,814 U1.2@1888.23,836.79 ; v1(1993.57,1772.16) 1994.74,1773.32 1994.74,1789.75 2023.24,1818.26 2078.06,1818.26 2136.46,1876.67 2251.14,1876.67 2295.32,1920.85 2295.32,1931.23 2331.75,1967.66 2360.19,1967.66 U2.9@2360.88,1968.34
  Bottom Layer w12: v1(1779.53,794.68) 1714.55,794.68 1538.59,970.65 1538.59,1342.58 1968.17,1772.16 v1(1993.57,1772.16)
SHB: U2.16 U4.2 | length 1419.7
  Top Layer w12: v1(2275.01,805.6) 2284.76,795.85 2366.19,795.85 2388.23,817.89 U4.2@2388.23,836.79 ; U2.16@2445.52,1883.7 2445.52,1651.58 2568.16,1528.94 2568.16,1528.45 2578.74,1517.87 v1(2578.74,1496.06)
  Bottom Layer w12: v1(2275.01,805.6) 2275.01,953.68 2352.27,1030.94 2378.36,1030.94 2578.74,1231.31 v1(2578.74,1496.06)
SHC: U2.19 U6.2 | length 1420.3
  Top Layer w12: U2.19@2504.58,1883.7 2504.58,1809.17 2519.31,1794.43 2519.31,1759.45 2651.63,1627.14 v1(2696.85,1627.14) ; v1(2817.34,787.4) 2817.34,779.05 2884.23,779.05 2917.63,812.45 2917.63,814.01 2918.11,814.49 U6.2@2918.11,836.59
  Bottom Layer w12: v1(2696.85,1627.14) 2723.01,1627.14 2802.3,1547.84 2802.3,1425.77 2816.16,1411.9 2816.16,856.04 2809.16,849.04 2809.16,824.19 2814.39,818.96 2814.39,790.35 v1(2817.34,787.4)
"SLEEP DRV8-1": TP13.1 U8.21 U21.1 | length 2172.3
  Top Layer w12: U8.21@3939.21,1502.1 3939.21,1515.09 v2(3959.55,1535.43) ; v2(4498.03,2920.65) 4500.71,2923.33 U21.1@4500.71,2967.84 4580.13,2967.84 v2(4607.47,2995.18)
  Signal Layer 2 w12: v2(3959.55,1535.43) 3959.55,1595.13 4052.01,1687.59 4107.8,1687.59 4298,1877.79 4298,2488.5 4498.03,2688.53 v2(4498.03,2920.65) ; v2(4607.47,2995.18) 4607.47,3250.41 TP13.1@4655.51,3298.45
"SLEEP DRV8-2": TP14.1 U8.27 U22.1 | length 2237.3
  Top Layer w12: v2(3817.63,1574.8) 3817.63,1554.15 3821.1,1550.68 U8.27@3821.1,1502.1 ; v2(3945.83,2913.39) 3947.2,2914.76 U22.1@3947.2,2967.17 3978.51,2967.17 4212.56,3201.22 4421.75,3201.22 4517.77,3297.24 TP14.1@4527.56,3297.24
  Signal Layer 2 w12: v2(3817.63,1574.8) 3900.94,1658.11 3900.94,2868.5 v2(3945.83,2913.39)
SOA: R27.1 U2.25 | length 1859.1
  Top Layer w12: U2.25@2628.59,1909.29 2663.33,1874.55 2740.69,1874.55 2740.97,1874.27 2742.89,1874.27 3033.88,1583.28 3352.3,1583.28 v2(3513.78,1421.8) ; v2(3736.44,907.94) 3816.93,827.45 R27.1@3816.93,775.37
  Signal Layer 2 w12: v2(3513.78,1421.8) 3623.5,1312.07 3623.5,1020.87 v2(3736.44,907.94)
SOB: R28.1 U2.24 | length 1848.6
  Top Layer w12: U2.24@2603,1883.7 2631.43,1855.27 2735.02,1855.27 3026.01,1564.28 3321.01,1564.28 v2(3477.81,1407.48) v2@3480.49,1404.8 ; R28.1@3695.12,724.74 v2(3695.12,901.46)
  Signal Layer 2 w12: v2(3477.81,1407.48) 3603.47,1281.82 3603.47,993.11 v2(3695.12,901.46)
SOC: R26.1 U2.23 | length 1936
  Top Layer w12: U2.23@2583.32,1883.7 2583.32,1857.59 2604.64,1836.27 2727.11,1836.27 3018.1,1545.28 3285.68,1545.28 v2(3439.1,1391.86) ; v2(3631.27,902.29) 3631.27,616.56 R26.1@3635.72,612.11
  Signal Layer 2 w12: v2(3439.1,1391.86) 3439.1,1373.9 3582.68,1230.32 3582.68,950.88 v2(3631.27,902.29)
SPA1: C1.2 R5.2 R13.1 U1.12 U1.13 U1.14 U1.15 U1.16 U1.17 U1.18 U1.19 U1.20 U3.9@1750,1107.09 | length 745.5
  Top Layer w12: R5.2@1824.33,1249.42 1864.21,1249.42 1899.61,1284.81 1899.61,1325.78 1929.13,1355.31 1929.13,1443.68 1970.99,1485.54 2165.94,1485.54 2184.3,1503.89 R13.1@2184.3,1708.3
  other v3: 1728.35,1107.09 1771.65,1107.09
